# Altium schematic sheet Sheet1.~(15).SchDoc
size A3
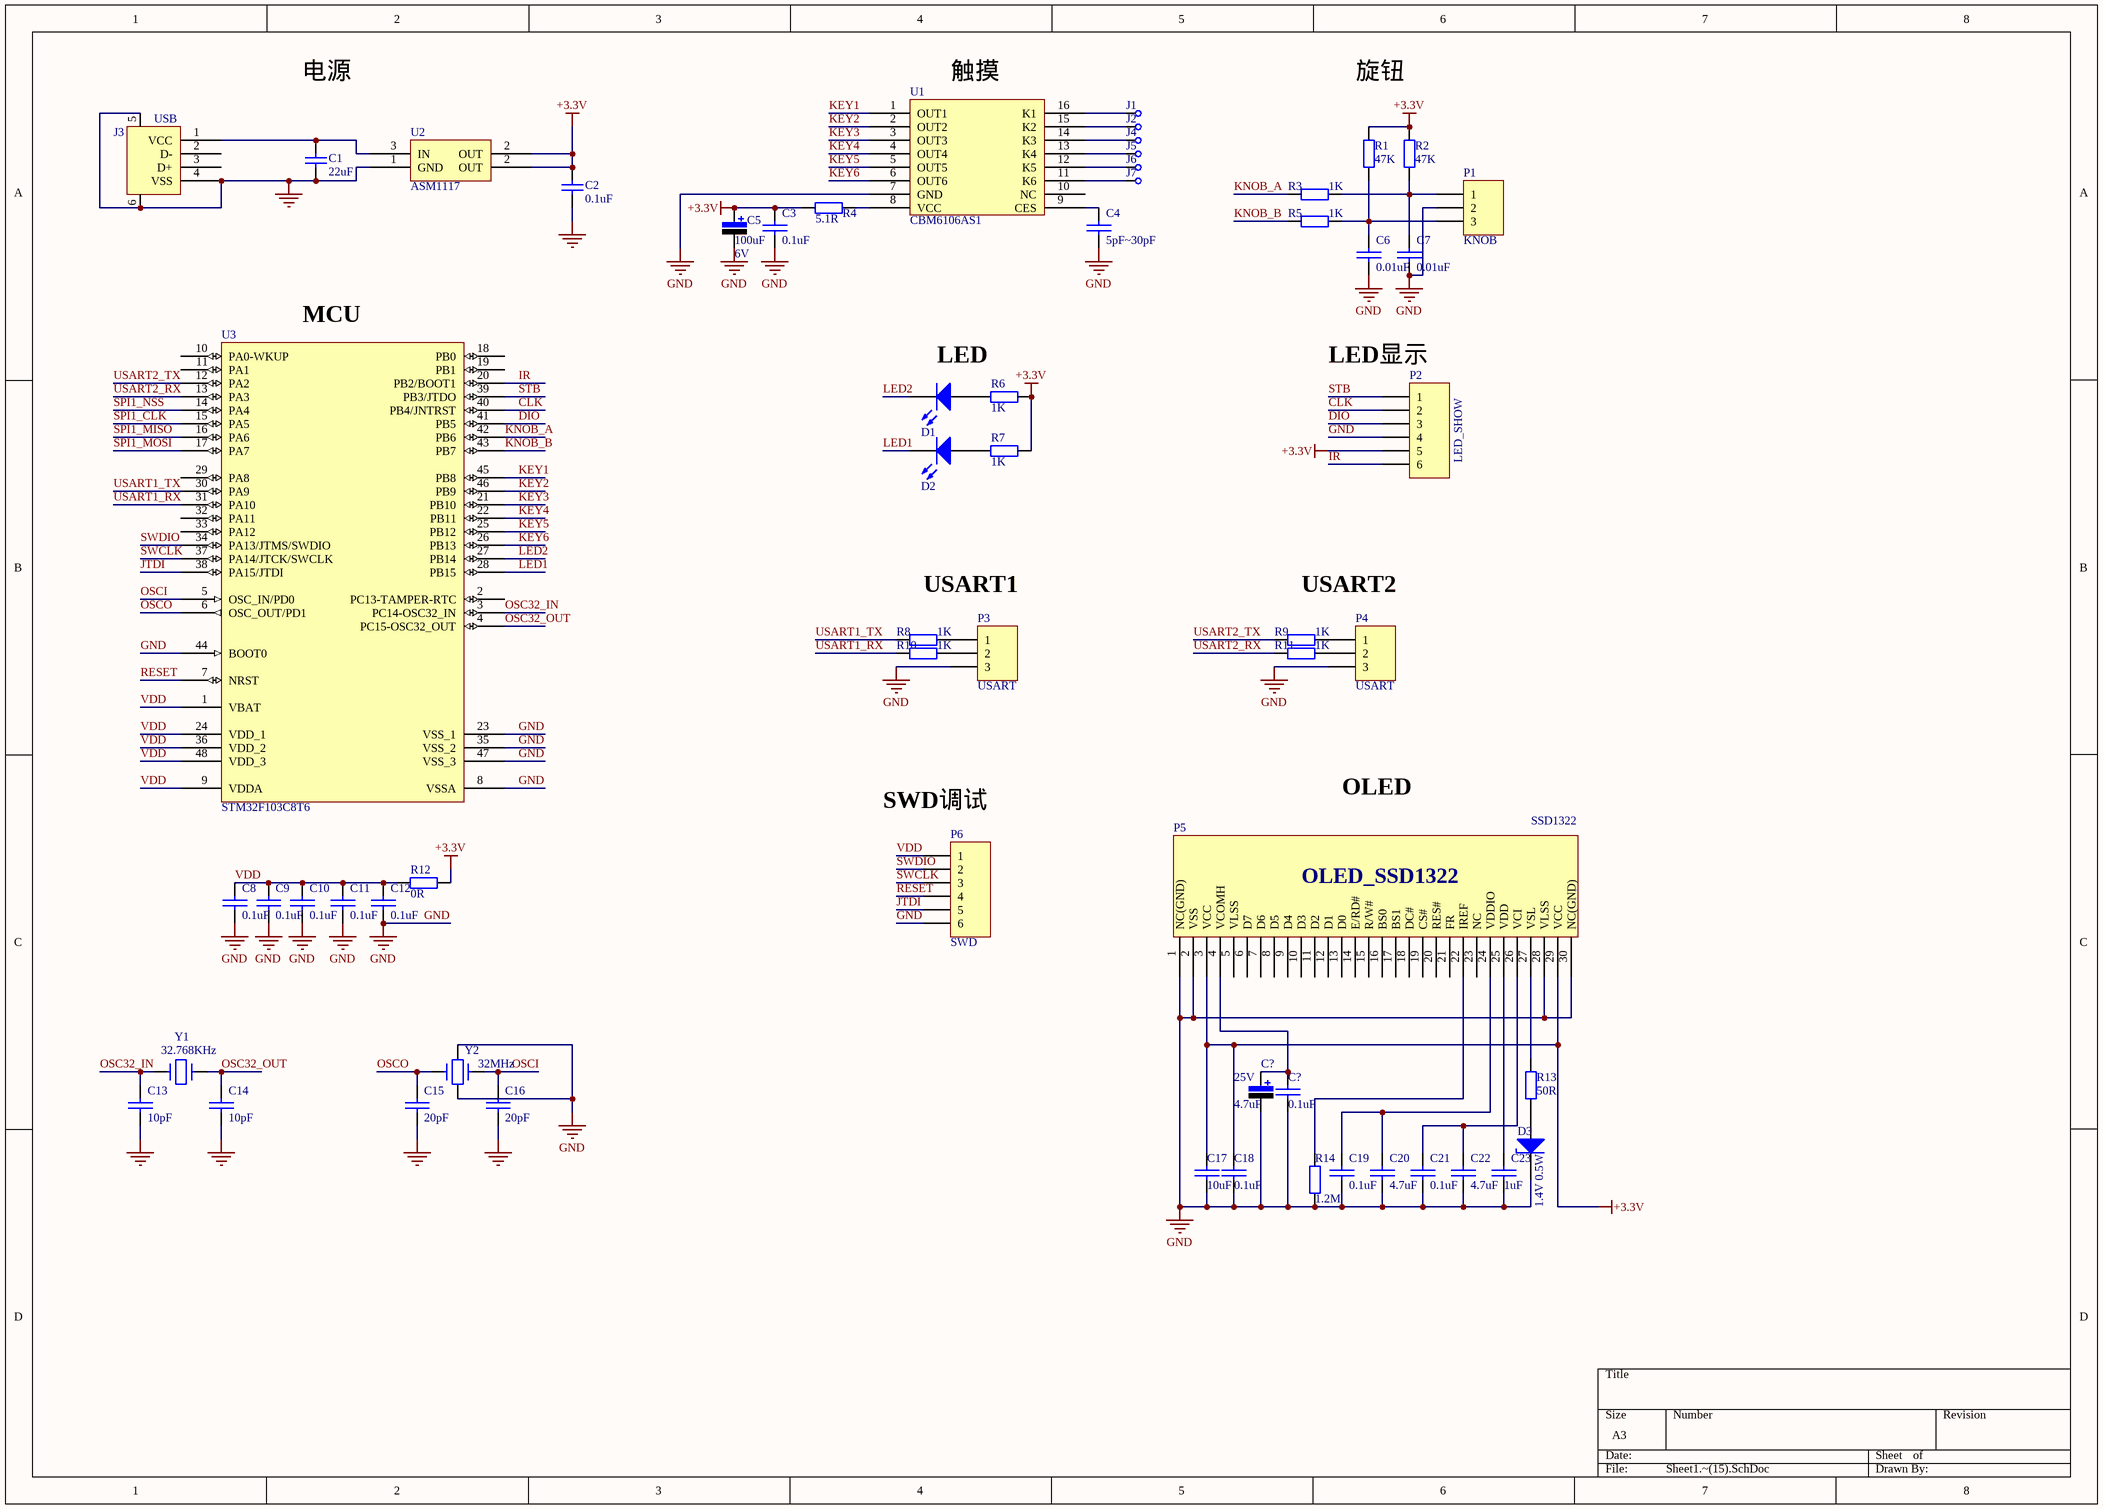
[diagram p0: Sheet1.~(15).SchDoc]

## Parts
(Parts that share a designator on the sheet are numbered #1, #2 ... from top to bottom, then left to right.)
C1  value 22uF  [0402C]  (hidden comment: Cap)
C2  value 0.1uF  [0402C]  (hidden comment: Cap)
C3  0.1uF  [0402C]
C4  5pF~30pF  [0402C]
C5  value 100uF  Vol: 6V  [CAP-3528]  (hidden comment: Cap Pol)
C6  0.01uF  [0402C]
C7  0.01uF  [0402C]
C8  0.1uF  [0402C]
C9  0.1uF  [0402C]
C10  0.1uF  [0402C]
C11  0.1uF  [0402C]
C12  0.1uF  [0402C]
C13  10pF  [0402C]
C14  10pF  [0402C]
C15  20pF  [0402C]
C16  20pF  [0402C]
C17  10uF  [0402C]
C18  0.1uF  [0402C]
C19  0.1uF  [0402C]
C20  4.7uF  [0402C]
C21  0.1uF  [0402C]
C22  4.7uF  [0402C]
C23  1uF  [0402C]
C?#1  value 4.7uF  Vol: 25V  [CAP-3528]  (hidden comment: Cap Pol)
C?#2  0.1uF  [0402C]
D1  LED0  [led0603]  (value not drawn)
D2  LED0  [led0603]  (value not drawn)
D3  value 1.4V 0.5W  [DIODE-1206]  (hidden comment: Diode-Z)
J1  CHECK  [CHECK-A]  (value not drawn)
J2  CHECK  [CHECK-A]  (value not drawn)
J3  USB  [USB_A1]
J4  CHECK  [CHECK-A]  (value not drawn)
J5  CHECK  [CHECK-A]  (value not drawn)
J6  CHECK  [CHECK-A]  (value not drawn)
J7  CHECK  [CHECK-A]  (value not drawn)
P1  KNOB  [HDR3X1_A]
P2  LED_SHOW  [HDR6X1_B2]
P3  USART  [HDR3X1_A]
P4  USART  [HDR3X1_A]
P5  SSD1322
P6  SWD  [HDR6X1_B2]
R1  value 47K  [0603-1]  (hidden comment: Res1)
R2  value 47K  [0603-1]  (hidden comment: Res1)
R3  value 1K  [0603-1]  (hidden comment: Res1)
R4  value 5.1R  [0603-1]  (hidden comment: Res1)
R5  value 1K  [0603-1]  (hidden comment: Res1)
R6  value 1K  [0402R]  (hidden comment: Res1)
R7  value 1K  [0402R]  (hidden comment: Res1)
R8  value 1K  [0402R]  (hidden comment: Res1)
R9  value 1K  [0402R]  (hidden comment: Res1)
R10  value 1K  [0402R]  (hidden comment: Res1)
R11  value 1K  [0402R]  (hidden comment: Res1)
R12  value 0R  [0402R]  (hidden comment: Res1)
R13  value 50R  [0402R]  (hidden comment: Res1)
R14  value 1.2M  [0402R]  (hidden comment: Res1)
U1  CBM6106AS1
U2  ASM1117  [SOT-223-3]
U3  STM32F103C8T6  [LQFP48_N]
Y1  32.768KHz  [SMD3215]
Y2  32MHz  [Y3225]

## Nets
+3.3V: C2.2 C3.1 C5.1 C17.1 C18.1 P2.5 P5.3(VCC) P5.29(VCC) R1.2 R2.2 R4.1 R6.1 R7.1 R12.2 U2.2(OUT)
GND: C1.1 C2.1 C3.2 C4.2 C5.2 C6.2 C7.2 C8.2 C9.2 C10.2 C11.2 C12.2 C13.2 C14.2 C15.2 C16.2 C17.2 C18.2 C19.2 C20.2 C21.2 C22.2 C23.2 C?#1.2 C?#2.2 D3.2(K) J3.4(VSS) J3.5 J3.6 P1.2 P2.4 P3.3 P4.3 P5.1(NC(GND)) P5.2(VSS) P5.28(VLSS) P5.30(NC(GND)) P6.6 R14.2 U1.7(GND) U2.1(GND) U3.8(VSSA) U3.23(VSS_1) U3.35(VSS_2) U3.44(BOOT0) U3.47(VSS_3) Y2.2 Y2.4
CLK: P2.2 U3.40(PB4/JNTRST)
DIO: P2.3 U3.41(PB5)
IR: P2.6 U3.20(PB2/BOOT1)
JTDI: P6.5 U3.38(PA15/JTDI)
KEY1: U1.1(OUT1) U3.45(PB8)
KEY2: U1.2(OUT2) U3.46(PB9)
KEY3: U1.3(OUT3) U3.21(PB10)
KEY4: U1.4(OUT4) U3.22(PB11)
KEY5: U1.5(OUT5) U3.25(PB12)
KEY6: U1.6(OUT6) U3.26(PB13)
KNOB_A: R3.1 U3.42(PB6)
KNOB_B: R5.1 U3.43(PB7)
LED1: D2.2(K) U3.28(PB15)
LED2: D1.2(K) U3.27(PB14)
OSC32_IN: C13.1 U3.3(PC14-OSC32_IN) Y1.1
OSC32_OUT: C14.1 U3.4(PC15-OSC32_OUT) Y1.2
OSCI: C16.1 U3.5(OSC_IN/PD0) Y2.3
OSCO: C15.1 U3.6(OSC_OUT/PD1) Y2.1
RESET: P6.4 U3.7(NRST)
SPI1_CLK: U3.15(PA5)
SPI1_MISO: U3.16(PA6)
SPI1_MOSI: U3.17(PA7)
SPI1_NSS: U3.14(PA4)
STB: P2.1 U3.39(PB3/JTDO)
SWCLK: P6.3 U3.37(PA14/JTCK/SWCLK)
SWDIO: P6.2 U3.34(PA13/JTMS/SWDIO)
USART1_RX: R10.2 U3.31(PA10)
USART1_TX: R8.2 U3.30(PA9)
USART2_RX: R11.2 U3.13(PA3)
USART2_TX: R9.2 U3.12(PA2)
VDD: C8.1 C9.1 C10.1 C11.1 C12.1 P6.1 R12.1 U3.1(VBAT) U3.9(VDDA) U3.24(VDD_1) U3.36(VDD_2) U3.48(VDD_3)
NetC1_2: C1.2 J3.1(VCC) U2.3(IN)
NetC4_1: C4.1 U1.9(CES)
NetC6_1: C6.1 P1.3 R1.1 R5.2
NetC7_1: C7.1 P1.1 R2.1 R3.2
NetC19_1: C19.1 C20.1 P5.24(VDDIO)
NetC21_1: C21.1 C22.1 P5.26(VCI)
NetC23_1: C23.1 P5.25(VDD)
NetC?#1_1: C?#1.1 C?#2.1 P5.4(VCOMH)
NetD1_1: D1.1(A) R6.2
NetD2_1: D2.1(A) R7.2
NetD3_1: D3.1(A) R13.2
NetJ1_1: J1.1 U1.16(K1)
NetJ2_1: J2.1 U1.15(K2)
NetJ4_1: J4.1 U1.14(K3)
NetJ5_1: J5.1 U1.13(K4)
NetJ6_1: J6.1 U1.12(K5)
NetJ7_1: J7.1 U1.11(K6)
NetP3_1: P3.1 R8.1
NetP3_2: P3.2 R10.1
NetP4_1: P4.1 R9.1
NetP4_2: P4.2 R11.1
NetP5_22: P5.22(IREF) R14.1
NetP5_27: P5.27(VSL) R13.1
NetR4_2: R4.2 U1.8(VCC)

Not connected (* = marked no-connect by the designer): J3 2(D-) 3(D+); P5 5(VLSS) 6(D7) 7(D6) 8(D5) 9(D4) 10(D3) 11(D2) 12(D1) 13(D0) 14(E/RD#) 15(R/W#) 16(BS0) 17(BS1) 18(DC#) 19(CS#) 20(RES#) 21(FR) 23(NC); U1 10(NC); U3 2(PC13-TAMPER-RTC) 10(PA0-WKUP) 11(PA1) 18(PB0) 19(PB1) 29(PA8) 32(PA11) 33(PA12)

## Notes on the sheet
- 电源
- (near U1) 触摸
- 旋钮
- (near U3) MCU
- LED
- (near P2) LED显示
- USART1
- USART2
- (near P6) SWD调试
- OLED

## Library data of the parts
C1 C2 = Cap: 无极性电容
C3 C4 C6-C23 C?#2 = CAP: Capacitor
C5 C?#1 = Cap Pol: 极性电解电容
D1 D2 = LED0: 发光二极管
D3 = Diode-Z: 稳压二极管
J1 J2 J4-J7 = CHECK: 测试点
J3 = USB: USB接口
P1 P3 P4 = Header 3: 接插件
P2 P6 = Header 6: 接插件
R1-R14 = Res1: 贴片电阻
U2 = ASM1117: 3.3V稳压芯片
U3 = STM32F103C8T6: STM32 ARM-based 32-bit MCU with 64 Kbytes Flash, 48-pin LQFP, Industrial Temperature
Y1 = CRYSTAL
Y2 = CRYSTAL1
